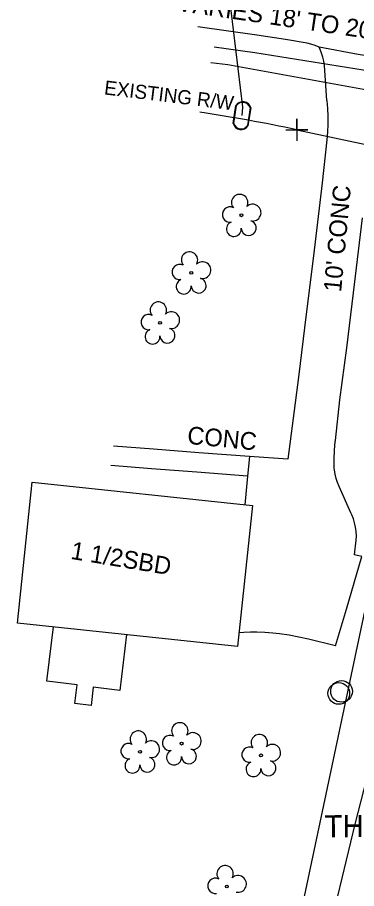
# Model space of a CAD drawing. Extents: x 1614611 to 1617571, y 898867 to 905462.
# Drawn here: x 1615943.2 to 1616020, y 899933.8 to 900131 of the extents above; entities that cross this region are included whole.
import ezdxf

# ---------------------------------------------------------------- set-up
doc = ezdxf.new("R2010")
doc.units = 0
for name, color, linetype in [('Exist Building', 7, 'Continuous'), ('Exist Building Text', 7, 'Continuous'), ('Exist Other Culture Area Outline', 7, 'Continuous'), ('Exist Other Culture Area Outline Text', 7, 'Continuous'), ('Exist Right of Way Line Text', 7, 'Continuous'), ('Exist Roads EOP Other Text', 7, 'Continuous'), ('Exist Roads EOT Text', 7, 'Continuous'), ('Exist Utilities Other Pole CELL', 7, 'Continuous'), ('Exist Utilities Sanitary Sewer Forced Main SUE LOS C', 7, 'Continuous'), ('Exist Utilities Telephone UG Cable SUE LOS C', 7, 'Continuous'), ('Exist Utilities Water UG Line SUE LOS B', 7, 'Continuous'), ('Exist Vegetation Tree CELL', 7, 'Continuous'), ('Prop Drainage Structure Pipe Alternate 30in Label', 7, 'Continuous'), ('Prop Drainage Structure Pipe Removal', 7, 'Continuous'), ('Prop Drainage Structure Tops and Inverts LABEL', 7, 'Continuous'), ('Prop Earthen Structure Head Ditch Label', 7, 'Continuous'), ('Prop SS Transition Line', 7, 'Continuous'), ('Scratch_Level_1', 7, 'Continuous'), ('Scratch_Level_9', 7, 'Continuous')]:
    doc.layers.add(name, color=color, linetype=linetype)

msp = doc.modelspace()

# ---------------------------------------------------------------- linework, layer by layer
at = {"layer": 'Exist Building'}
msp.add_lwpolyline([(1615993.09, 899988.61), (1615943.18, 899993.9), (1615946.55, 900025.77), (1615996.46, 900020.48)], close=True, dxfattribs=at)
msp.add_lwpolyline([(1615997.46, 899991.84), (1615995.98, 899991.81), (1615994.47, 899991.74), (1615993.41, 899991.65)], dxfattribs=at)
at = {"layer": 'Exist Other Culture Area Outline'}
for points in [[(1615995.78, 900031.61), (1615984.29, 900032.47), (1615974, 900033.24), (1615964.99, 900033.95)], [(1615995.34, 900027.18), (1615983.86, 900028.05), (1615973.57, 900028.83), (1615964.33, 900029.54)], [(1615967.87, 899991.29), (1615966.36, 899978.62), (1615960.38, 899979.34), (1615959.9, 899975.26), (1615956.22, 899975.69), (1615956.72, 899979.88), (1615949.88, 899980.7), (1615951.35, 899993.04)]]:
    msp.add_lwpolyline(points, dxfattribs=at)
at = {"layer": 'Exist Utilities Other Pole CELL'}
for centre in [(1616016.01, 899977.97), (1616016.64, 899978.43)]:
    msp.add_circle(centre, 2.46, dxfattribs=at)
at = {"layer": 'Exist Utilities Sanitary Sewer Forced Main SUE LOS C'}
msp.add_lwpolyline([(1615987.8, 900124.36), (1615996.95, 900123.07), (1616029.07, 900117.94), (1616050.03, 900113.65), (1616071.5, 900109.18), (1616143.09, 900093.88), (1616176.95, 900086.31), (1616208.03, 900078.35), (1616239.83, 900068.88), (1616305.38, 900049.26)], dxfattribs=at)
at = {"layer": 'Exist Utilities Telephone UG Cable SUE LOS C'}
msp.add_lwpolyline([(1615987.03, 900120.84), (1615990.86, 900120.34), (1616033.24, 900112.71), (1616040.14, 900111.41), (1616043.65, 900109.9), (1616045.95, 900108.2), (1616046.15, 900106.5), (1616046.08, 900103.84), (1616045.66, 900098.32)], dxfattribs=at)
at = {"layer": 'Exist Utilities Water UG Line SUE LOS B'}
msp.add_lwpolyline([(1615993.99, 900150.57), (1615993.68, 900146.49), (1615991.58, 900132.6), (1615994.22, 900110.73), (1615994.06, 900108.79)], dxfattribs=at)
at = {"layer": 'Exist Vegetation Tree CELL'}
for p, q in [((1615993.94, 900086.24), (1615993.94, 900086.24)), ((1615982.57, 900073.21), (1615982.57, 900073.21)), ((1615975.5, 900061.88), (1615975.5, 900061.88)), ((1615980.38, 899966.59), (1615980.38, 899966.59)), ((1615970.96, 899964.73), (1615970.96, 899964.73)), ((1615998.38, 899963.93), (1615998.38, 899963.93)), ((1615990.63, 899934.23), (1615990.63, 899934.23))]:
    msp.add_line(p, q, dxfattribs=at)
for centre in [(1615993.94, 900086.24), (1615982.57, 900073.21), (1615975.5, 900061.88), (1615980.38, 899966.59), (1615970.96, 899964.73), (1615998.38, 899963.93), (1615990.63, 899934.23)]:
    msp.add_circle(centre, 0.326, dxfattribs=at)
for centre, radius, start, end in [((1615993.55, 900089.11), 1.86, 330.1651, 219.7134), ((1615991.33, 900086.4), 1.73, 62.6636, 279.3457), ((1615996.49, 900086.83), 1.9, 257.1011, 134.1999), ((1615992.24, 900083.12), 1.69, 111.5671, 6.231), ((1615995.61, 900083.34), 1.7, 181.2822, 74.56), ((1615982.19, 900076.09), 1.86, 330.1651, 219.7134), ((1615979.97, 900073.37), 1.73, 62.6636, 279.3457), ((1615985.12, 900073.8), 1.9, 257.1011, 134.1999), ((1615984.25, 900070.32), 1.7, 181.2822, 74.56), ((1615980.87, 900070.09), 1.69, 111.5671, 6.231), ((1615975.12, 900064.75), 1.86, 330.1651, 219.7134), ((1615978.05, 900062.47), 1.9, 257.1011, 134.1999), ((1615972.9, 900062.03), 1.73, 62.6636, 279.3457), ((1615973.8, 900058.76), 1.69, 111.5671, 6.231), ((1615977.18, 900058.98), 1.7, 181.2822, 74.56), ((1615979.99, 899969.47), 1.86, 330.1651, 219.7134), ((1615970.57, 899967.61), 1.86, 330.1651, 219.7134), ((1615977.77, 899966.75), 1.73, 62.6636, 279.3457), ((1615982.93, 899967.18), 1.9, 257.1011, 134.1999), ((1615998, 899966.8), 1.86, 330.1651, 219.7134), ((1615968.35, 899964.89), 1.73, 62.6636, 279.3457), ((1615973.51, 899965.32), 1.9, 257.1011, 134.1999), ((1615995.78, 899964.08), 1.73, 62.6636, 279.3457), ((1616000.93, 899964.52), 1.9, 257.1011, 134.1999), ((1615972.63, 899961.83), 1.7, 181.2822, 74.56), ((1615978.67, 899963.47), 1.69, 111.5671, 6.231), ((1615982.05, 899963.7), 1.7, 181.2822, 74.56), ((1615969.25, 899961.61), 1.69, 111.5671, 6.231), ((1615996.68, 899960.81), 1.69, 111.5671, 6.231), ((1616000.06, 899961.03), 1.7, 181.2822, 74.56), ((1615990.25, 899937.11), 1.86, 330.1651, 219.7134), ((1615988.02, 899934.39), 1.73, 62.6636, 279.3457), ((1615993.18, 899934.82), 1.9, 257.1011, 134.1999)]:
    msp.add_arc(centre, radius, start, end, dxfattribs=at)
at = {"layer": 'Prop Drainage Structure Pipe Alternate 30in Label'}
msp.add_lwpolyline([(1616043.33, 900097.76), (1615994.84, 899869.26)], dxfattribs=at)
at = {"layer": 'Prop Drainage Structure Tops and Inverts LABEL'}
msp.add_line((1616006.49, 900105.58), (1616006.49, 900105.58), dxfattribs=at)
msp.add_lwpolyline([(1616003.99, 900105.58), (1616008.99, 900105.58), (1616006.49, 900105.58), (1616006.49, 900108.08), (1616006.49, 900103.08)], dxfattribs=at)
at = {"layer": 'Prop Earthen Structure Head Ditch Label'}
msp.add_line((1616006.49, 900105.58), (1616248.81, 900054.12), dxfattribs=at)
msp.add_arc((1615927.55, 899733.9), 379.98, 78.0094, 81.3727, dxfattribs=at)
at = {"layer": 'Prop SS Transition Line'}
msp.add_line((1615994.06, 900108.79), (1615994.06, 900108.79), dxfattribs=at)
for points in [[(1615992.07, 900107.04), (1615992.7, 900111.09)], [(1615992.21, 900107.02), (1615992.83, 900111.07)], [(1615995.92, 900110.57), (1615995.3, 900106.54)], [(1615996.05, 900110.55), (1615995.43, 900106.52)]]:
    msp.add_lwpolyline(points, dxfattribs=at)
for centre, radius, start, end in [((1615994.26, 900110.09), 1.86, 14.4456, 147.2469), ((1615994.25, 900110.08), 1.73, 16.5685, 145.0499), ((1615993.87, 900107.52), 1.86, 194.9159, 327.5759), ((1615993.87, 900107.5), 1.73, 196.3947, 326.1404)]:
    msp.add_arc(centre, radius, start, end, dxfattribs=at)
at = {"layer": 'Scratch_Level_1'}
for points in [[(1616013.3, 900112.2), (1616012.74, 900120.14), (1616012.61, 900121.09), (1616012.4, 900122.01), (1616012.12, 900122.92), (1616011.76, 900123.8), (1616011.54, 900124.26)], [(1616012.31, 899916.12), (1616015.81, 899932.04), (1616019.74, 899948.33), (1616023.09, 899961.54), (1616025.7, 899971.93), (1616029.37, 899988.28), (1616033.06, 900005.31), (1616036.82, 900023.1), (1616040.19, 900040.3), (1616044.56, 900061.74), (1616048.08, 900079.48), (1616051.05, 900093.96), (1616052.72, 900101.57), (1616052.92, 900102.87), (1616053.04, 900104.17), (1616053.08, 900105.48), (1616053.05, 900106.8), (1616052.93, 900108.1), (1616052.9, 900108.34), (1616051.05, 900117.61)], [(1616013.3, 900112.2), (1616013.46, 900110.42), (1616013.54, 900108.64), (1616013.54, 900106.86), (1616013.46, 900105.08), (1616013.3, 900103.32), (1616012.27, 900093.54), (1616010.31, 900077.07), (1616008.62, 900063.86), (1616006.9, 900049.55), (1616004.49, 900030.99), (1615995.78, 900031.61), (1615995.34, 900027.18), (1615994.7, 900020.67)], [(1616015.29, 899988.77), (1616017.74, 899997.06), (1616021.23, 900008.93), (1616019.61, 900009.33), (1616019.96, 900012.63), (1616019.99, 900013.62), (1616019.94, 900014.61), (1616019.82, 900015.59), (1616019.6, 900016.56), (1616019.32, 900017.51), (1616018.97, 900018.43), (1616018.78, 900018.85), (1616016.07, 900024.83), (1616015.69, 900025.73), (1616015.39, 900026.66), (1616015.17, 900027.6), (1616015.03, 900028.57), (1616014.99, 900028.96), (1616014.99, 900030.99), (1616015.06, 900033.01), (1616015.21, 900035.03), (1616015.23, 900035.21), (1616016.27, 900044.43), (1616017.82, 900056.18), (1616019.36, 900068.68), (1616021.4, 900085.62)], [(1616015.29, 899988.77), (1616009.16, 899990.24), (1616006.99, 899990.72), (1616004.8, 899991.12), (1616002.6, 899991.45), (1616001.08, 899991.64), (1615999.28, 899991.79), (1615997.46, 899991.84)]]:
    msp.add_lwpolyline(points, dxfattribs=at)
at = {"layer": 'Scratch_Level_9'}
msp.add_lwpolyline([(1616059.36, 900116.09), (1616053.63, 900117.24), (1616051.05, 900117.61), (1616048.3, 900118.39), (1616044.34, 900119.28), (1616039.93, 900120.18), (1616034.88, 900121), (1616030.42, 900121.62), (1616029.55, 900121.68), (1616028.68, 900121.66), (1616027.82, 900121.57), (1616027.59, 900121.53), (1616020.38, 900122.62), (1616011.54, 900124.26), (1616010.63, 900124.65), (1616009.7, 900124.98), (1616008.82, 900125.22), (1616003.94, 900126.01), (1615997.44, 900126.99), (1615984.1, 900128.9)], dxfattribs=at)

# ---------------------------------------------------------------- texts
at = {"layer": 'Exist Building Text'}
msp.add_text('1 1/2SBD', height=4, rotation=350.6505, dxfattribs=at).set_placement((1615955.08, 900008.45))
at = {"layer": 'Exist Other Culture Area Outline Text'}
msp.add_text('CONC', height=4, rotation=354.4606, dxfattribs=at).set_placement((1615981.54, 900034.5))
at = {"layer": 'Exist Right of Way Line Text'}
msp.add_text('EXISTING R/W', height=3.2, rotation=353.0004, dxfattribs=at).set_placement((1615962.72, 900113.61))
at = {"layer": 'Exist Roads EOP Other Text'}
msp.add_text("10' CONC", height=4, rotation=84.6884, dxfattribs=at).set_placement((1616016.54, 900068.75))
at = {"layer": 'Exist Roads EOT Text'}
msp.add_text("VARIES 18' TO 20' BST", height=4, rotation=351.6581, dxfattribs=at).set_placement((1615979.23, 900132.56))
at = {"layer": 'Prop Drainage Structure Pipe Removal'}
msp.add_text('THOMAS ANDREW PARISH', height=5, rotation=0.286, dxfattribs=at).set_placement((1616012.78, 899945.38))

doc.saveas('drawing.dxf')
